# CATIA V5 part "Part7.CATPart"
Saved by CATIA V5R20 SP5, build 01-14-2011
Part number: 中左
Bounding box of the stored display mesh (mm): x 40.887 to 99.851, y -5 to 5, z -150.472 to 1.581
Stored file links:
  E:\180511232\很靠后、\Part7.CATPart
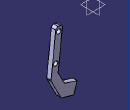
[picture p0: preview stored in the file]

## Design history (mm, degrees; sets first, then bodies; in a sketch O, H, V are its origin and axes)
Body1 (main body)
  Sketch1 on zx-plane, origin (0, 0, 0), H (-1, 0, 0), V (0, 0, 1)
    line L1 (-88.7834, 2.1431) -> (-73.8784, 0.4573)
    line L2 (-73.8784, 0.4573) -> (-83.9928, -88.9725)
    line L3 (-100.0216, -97.2234) -> (-88.7834, 2.1431)
    point P3 (-100.0216, -97.2234)
    circle A1 centre (-82.4547, -8.6365) radius 5
    point P4 (-82.4547, -8.6365)
    line L4 (-83.9928, -88.9725) -> (-100.0216, -97.2234)
    point P6 (-100.0216, -97.2234)
    radius A1 = 5
    length L1 = 15
    distance P4 L3 = 7.5
    distance P4 L1 = 10
    length L2 = 90
    length L3 = 100
    parallelism: L3 L2
    perpendicularity: L1 L2
    coincidence: P6 L3, L4 P3, P3 P6
Body2
  Pad1: profile Sketch1, direction (0, 1, 0), length 5, mirrored extent
  Sketch2 on zx-plane, origin (0, 0, 0), H (-1, 0, 0), V (0, 0, 1)
    line L1 (-83.9928, -88.9725) -> (-100.0216, -97.2234)
    point P1 (-83.9928, -88.9725)
    point P2 (-100.0216, -97.2234)
    line L2 (-100.0216, -97.2234) -> (-77.1376, -141.6793)
    line L3 (-77.1376, -141.6793) -> (-61.1088, -133.4284)
    line L4 (-61.1088, -133.4284) -> (-83.9928, -88.9725)
    reference projected point E1 (-83.9928, -88.9725) from vertex [face of Pad1 from Sketch1.L2 | end face of Pad1 | face of Pad1 from Sketch1.L4]
    reference projected point E2 (-100.0216, -97.2234) from vertex [face of Pad1 from Sketch1.L4 | end face of Pad1 | face of Pad1 from Sketch1.L3]
    distance P1 E1 = 0
    distance P2 E2 = 0
    length L2 = 50
    parallelism: L4 L2, L1 L3
    perpendicularity: L1 L2
  Pad2: profile Sketch2, direction (0, 1, 0), length 5, mirrored extent
  Fillet1: radius 5, on edge [face of Pad2 from Sketch2.L2 | face of Pad1 from Sketch1.L3]
  Fillet2: radius 5, on edge [face of Pad1 from Sketch1.L2 | face of Pad2 from Sketch2.L4]
  Fillet3: radius 5, on edge [face of Pad1 from Sketch1.L3 | face of Pad1 from Sketch1.L1]; edge [face of Pad1 from Sketch1.L1 | face of Pad1 from Sketch1.L2]
  Sketch3 on zx-plane, origin (0, 0, 0), H (-1, 0, 0), V (0, 0, 1)
    line L1 (-77.1376, -141.6793) -> (-69.5696, -116.9921)
    point P1 (-77.1376, -141.6793)
    point P2 (-69.5696, -116.9921)
    line L2 (-69.5696, -116.9921) -> (-40.8871, -125.7849)
    line L3 (-40.8871, -125.7849) -> (-48.4551, -150.4722)
    line L4 (-48.4551, -150.4722) -> (-77.1376, -141.6793)
    reference projected line E1 (-61.1088, -133.4284) -> (-83.9928, -88.9725) from edge [face of Pad2 from Sketch2.L4 | face of Pad2]
    reference projected point E2 (-77.1376, -141.6793) from vertex [face of Pad2 from Sketch2.L3 | end face of Pad2 | face of Pad2 from Sketch2.L2]
    reference projected point E3 (-83.2999, -90.3185) from vertex [face of Pad2 from Sketch2.L4 | face of Fillet2 | face of Pad2]
    distance P2 E1 = 0
    distance P1 E2 = 0
    distance P2 E3 = 30
    length L4 = 30
    parallelism: L4 L2, L1 L3
    perpendicularity: L1 L2
  Pad3: profile Sketch3, direction (0, 1, 0), length 5, mirrored extent
  Fillet4: radius 5, on edge [face of Pad3 from Sketch3.L4 | face of Pad2 from Sketch2.L2]; edge [face of Pad2 from Sketch2.L4 | face of Pad3 from Sketch3.L2]
  Sketch4 on face of Pad3, origin (0, 5, 0), H (-1, 0, 0), V (0, 0, 1)
    circle A1 centre (-89.1976, -68.2564) radius 5
    point P1 (-89.1976, -68.2564)
    reference projected line E1 (-88.7834, 2.1431) -> (-100.0216, -97.2234) from edge [face of Pad1 from Sketch1.L3 | face of Pad3]
    reference projected line E2 (-73.8784, 0.4573) -> (-88.7834, 2.1431) from edge [face of Pad1 from Sketch1.L1 | face of Pad3]
    radius A1 = 5
    distance P1 E1 = 7.5
    distance P1 E2 = 70
  Pocket1: profile Sketch4, direction (0, -1, 0), length 10, mirrored extent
